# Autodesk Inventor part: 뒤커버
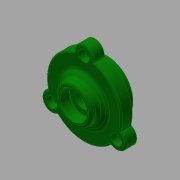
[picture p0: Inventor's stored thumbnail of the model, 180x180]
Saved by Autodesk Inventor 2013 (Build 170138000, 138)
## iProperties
Created: 2016-05
Part Number: 뒤커버
Document SubType Name: Modeling
Designer: mduedu
Density: 2.71 g/cm^3
Material: 알루미늄 6061
Author: mduedu
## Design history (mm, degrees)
sketch "스케치1"
  geometry: C1 r 20 at (0, 0); C2 r 27.5 at (0, 0); 1 further point
  constraints: 2 centre point, 2 coincident
  dimensions: "d33" = 55 diameter of C2; "d34" = 40 diameter of C1
extrude "돌출1" new body sketch "스케치1" distance "d0" = 8; taper "d1" = 0 deg
extrude "돌출2" join sketch "스케치1" distance "d2" = 8; taper "d3" = 0 deg; dims "d35" = 9, "d36" = 0
sketch "스케치5"
  geometry: L1 (-27.5, 8)-(27.5, 8) reference; L2 (0, 0)-(0, 15); L3 (-27.5, 0)-(27.5, 0) reference; L4 (17.5, 8)-(0, 8); A1 r 25.375 centre (0, -10.375) between (17.5, 8) and (0, 15)
  constraints: 4 end point, 3 point on line, 2 point on circle, 1 centre point, 1 midpoint, 1 perpendicular
  dimensions: "d37" = 17.5 distance from line of L2 L4.start; "d39" = 7 distance from line of L1 L2.end
revolve "회전2" sketch "스케치5" stored, may be unused: angle "d40" = 90 deg
node "작업 평면1"
sketch "스케치6"
  geometry: C1 r 13.5 at (0, 0); 1 further point
  constraints: 1 centre point, 1 coincident
  dimensions: "d42" = 27 diameter of C1
extrude "돌출4" join sketch "스케치6" stored distance "d43" = 10; taper "d44" = 0 deg
sketch "스케치4"
  geometry: L1 (0, -9)-(0, 16); L2 (-15, -9)-(-15, 0); L3 (-15, 0)-(-10, 0); L4 (-10, 0)-(-10, 3); L5 (-10, 3)-(-6, 3); L6 (-6, 3)-(-6, 8.6); L7 (-6, 8.6)-(-10, 8.6); L8 (-10, 8.6)-(-10, 16); L9 (20, -9)-(-20, -9) reference; L10 (-13.5, 16)-(13.5, 16) reference; 1 further point
  constraints: 16 end point, 6 parallel, 3 point on line, 2 midpoint, 1 perpendicular, 1 vertical
  dimensions: "d15" = 30 diameter of L2 L1; "d16" = 20 diameter of L8 L1; "d18" = 9 distance of L2.start L2.end; "d19" = 3 distance of L3.end L4.end; "d20" = 20 diameter of L4 L1; "d21" = 12 diameter of L6 L1; "d45" = 7.4 distance of L7.end L8.end
revolve "회전1" sketch "스케치4" stored, may be unused: angle "d22" = 90 deg
fillet "모깎기2" dims "d23" = 3
fillet "모깎기3" dims "d24" = 0.3
chamfer "모따기2" distance "d46" = 1; stored, may be unused: second distance "d47" = 2, angle "d48" = 45 deg
fillet "모깎기4" dims "d49" = 3
fillet "모깎기5" dims "d50" = 2
sketch "스케치7"
  geometry: C1 r 7 at (0, 27.5); 2 further points
  constraints: 3 vertical alignment, 1 centre point, 2 other
  dimensions: "d54" = 14 diameter of C1
extrude "돌출5" join sketch "스케치7" stored distance "d55" = 10; taper "d56" = 0 deg
fillet "모깎기6" dims "d57" = 1
fillet "모깎기7" dims "d61" = 1
sketch "스케치8" dims "d62" = 55 (derived)
  geometry: C1 r 18.661 at (0, 0) reference; A1 r 2 centre (-7.999, 27.355) between (-7.437, 25.435) and (-5.999, 27.391) reference; A2 r 26.5 centre (0, 0) between (-7.437, 25.435) and (-25.746, -6.277) reference; A3 r 2 centre (-27.689, -6.75) between (-26.721, -8.5) and (-25.746, -6.277) reference; A4 r 6 centre (-23.816, -13.75) between (-26.721, -8.5) and (-20.722, -18.891) reference; A5 r 2 centre (-19.69, -20.604) between (-18.309, -19.158) and (-20.722, -18.891) reference; A6 r 26.5 centre (0, 0) between (-18.309, -19.158) and (18.309, -19.158) reference; A7 r 2 centre (19.69, -20.604) between (20.722, -18.891) and (18.309, -19.158) reference; A8 r 6 centre (23.816, -13.75) between (20.722, -18.891) and (26.721, -8.5) reference; A9 r 2 centre (27.689, -6.75) between (25.746, -6.277) and (26.721, -8.5) reference; A10 r 26.5 centre (0, 0) between (25.746, -6.277) and (7.437, 25.435) reference; A11 r 2 centre (7.999, 27.355) between (5.999, 27.391) and (7.437, 25.435) reference; A12 r 6 centre (0, 27.5) between (5.999, 27.391) and (-5.999, 27.391) reference; 4 further points
  constraints: 2 coincident, 1 vertical alignment, 6 other
  dimensions: "d65" = 360 deg dimension on A2.centre point (0, 27.5) (derived)
sketch "스케치9"
  geometry: 3 further points
  constraints: 3 other
hole "구멍2" sketch "스케치9" at (-23.816, -13.75), (23.816, -13.75), (0, 27.5) diameter "d67" = 4.5; stored, may be unused: countersink angle "d71" = 90 deg, drill point angle "d73" = 0 deg; dims "d68" = 6, "d69" = 8, "d70" = 4.6, "d72" = 8
chamfer "모따기3" distance "d76" = 0.7; stored, may be unused: second distance "d77" = 2, angle "d78" = 30 deg
node "솔리드1"
pattern_circular "원형 패턴1" dims angle "d59" = 360 deg
other parameters: "d41" = 8
